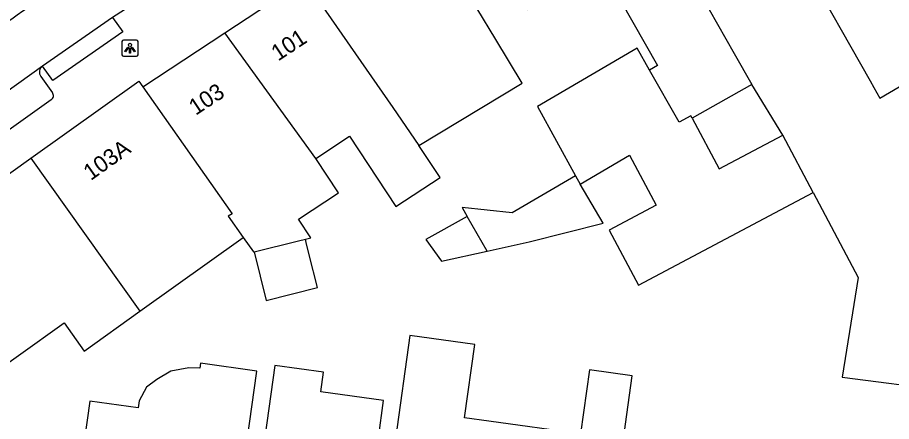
# Model space of a CAD drawing. Extents: x 159718 to 160783, y 383290 to 384030.
# Drawn here: x 160447.6 to 160501.3, y 383337.2 to 383362.1 of the extents above; entities that cross this region are included whole.
import ezdxf

# ---------------------------------------------------------------- set-up
doc = ezdxf.new("R2010")
doc.units = 0
for name, color, linetype in [('IMGEO_Lichtpunt', 7, 'Continuous'), ('IMGEO_Pand', 7, 'Continuous'), ('IMGEO_Pand_nummerreeks', 7, 'Continuous'), ('IMGEO_Rijbaan_lokaal_open', 7, 'Continuous'), ('IMGEO_Voetpad_open', 7, 'Continuous')]:
    doc.layers.add(name, color=color, linetype=linetype)

msp = doc.modelspace()

# ---------------------------------------------------------------- linework, layer by layer
at = {"layer": 'IMGEO_Lichtpunt'}
for p, q in [((160453.989, 383360.581), (160453.989, 383359.774)), ((160453.989, 383360.581), (160453.989, 383359.774)), ((160454.891, 383360.676), (160454.083, 383360.676)), ((160454.891, 383360.676), (160454.083, 383360.676)), ((160454.985, 383359.774), (160454.985, 383360.581)), ((160454.985, 383359.774), (160454.985, 383360.581)), ((160454.083, 383359.68), (160454.891, 383359.68)), ((160454.083, 383359.68), (160454.891, 383359.68))]:
    msp.add_line(p, q, dxfattribs=at)
for points in [[(160454.363, 383360.245), (160454.402, 383360.217), (160454.214, 383359.955), (160454.176, 383359.982), (160454.363, 383360.245)], [(160454.465, 383360.197), (160454.512, 383360.197), (160454.512, 383359.875), (160454.465, 383359.875), (160454.465, 383360.197)], [(160454.575, 383360.217), (160454.613, 383360.244), (160454.8, 383359.982), (160454.761, 383359.954), (160454.575, 383360.217)]]:
    msp.add_lwpolyline(points, dxfattribs=at)
msp.add_circle((160454.488, 383360.379), 0.0994, dxfattribs=at)
for centre, start, end in [((160454.083, 383360.581), 90, 180), ((160454.083, 383360.581), 90, 180), ((160454.891, 383360.581), 0, 90), ((160454.891, 383360.581), 0, 90), ((160454.083, 383359.774), 180, 270), ((160454.083, 383359.774), 180, 270), ((160454.891, 383359.774), 270, 0), ((160454.891, 383359.774), 270, 360)]:
    msp.add_arc(centre, 0.0946, start, end, dxfattribs=at)
at = {"layer": 'IMGEO_Pand'}
for points in [[(160482.934, 383375.203), (160491.645, 383359.858), (160492.727, 383357.952)], [(160474.49, 383370.418), (160476.949, 383366.065), (160478.765, 383362.85), (160478.932, 383362.554), (160481.205, 383363.833), (160482.02, 383364.291), (160482.405, 383363.614), (160483.893, 383364.459), (160486.934, 383359.106), (160486.44, 383358.826)], [(160472.243, 383354.191), (160478.604, 383358.023), (160476.988, 383360.706), (160474.653, 383364.584), (160472.034, 383368.843)], [(160495.919, 383365.354), (160500, 383358.164), (160500.229, 383357.761), (160500.597, 383357.113), (160504.871, 383359.614), (160506.61, 383356.155), (160506.076, 383351.936), (160510.595, 383351.363)], [(160460.32, 383361.128), (160465.222, 383364.356)], [(160465.222, 383364.356), (160470.655, 383356.532), (160472.243, 383354.191)], [(160455.281, 383357.809), (160460.32, 383361.128)], [(160465.92, 383353.41), (160460.32, 383361.128)], [(160486.44, 383358.826), (160485.672, 383360.178), (160479.547, 383356.594), (160481.887, 383352.339)], [(160489.062, 383355.871), (160488.983, 383356.02), (160488.253, 383355.633), (160486.44, 383358.826)], [(160448.396, 383353.416), (160455.036, 383358.149), (160455.281, 383357.809)], [(160492.727, 383357.952), (160489.062, 383355.871)], [(160494.636, 383354.831), (160492.727, 383357.952)], [(160455.281, 383357.809), (160460.761, 383350.009), (160460.533, 383349.859), (160461.455, 383348.546)], [(160489.062, 383355.871), (160490.72, 383352.755), (160494.636, 383354.831)], [(160465.92, 383353.41), (160467.985, 383354.772), (160470.84, 383350.442), (160473.567, 383352.239), (160472.243, 383354.191)], [(160496.503, 383351.311), (160494.636, 383354.831)], [(160482.17, 383351.824), (160485.208, 383353.602), (160486.836, 383350.53), (160483.956, 383349.003), (160485.753, 383345.612), (160496.503, 383351.311)], [(160439.387, 383346.996), (160448.396, 383353.416)], [(160448.396, 383353.416), (160455.096, 383344.015)], [(160465.277, 383348.446), (160465.604, 383348.527), (160464.85, 383349.671), (160467.314, 383351.295), (160465.92, 383353.41)], [(160481.887, 383352.339), (160477.991, 383350.058), (160474.917, 383350.38), (160475.224, 383349.845)], [(160481.887, 383352.339), (160482.17, 383351.824)], [(160476.45, 383347.71), (160479.029, 383348.286), (160483.594, 383349.424), (160482.17, 383351.824)], [(160496.503, 383351.311), (160499.273, 383346.085), (160498.286, 383339.955), (160504.652, 383339.145)], [(160475.224, 383349.845), (160472.682, 383348.427), (160473.649, 383347.085), (160476.45, 383347.71)], [(160476.45, 383347.71), (160475.224, 383349.845)], [(160455.096, 383344.015), (160461.455, 383348.546)], [(160461.455, 383348.546), (160462.079, 383347.657), (160462.118, 383347.667)], [(160462.118, 383347.667), (160464.847, 383348.341), (160465.277, 383348.446)], [(160462.118, 383347.667), (160462.856, 383344.682), (160466.014, 383345.463), (160465.513, 383347.49), (160465.328, 383348.24), (160465.277, 383348.446)], [(160444.801, 383339.293), (160450.429, 383343.303), (160451.665, 383341.569), (160455.096, 383344.015)], [(160485.367, 383340.053), (160482.742, 383340.419), (160482.192, 383336.474), (160476.551, 383337.261), (160475.059, 383337.469), (160475.686, 383341.966), (160471.698, 383342.522), (160470.814, 383336.177), (160470.215, 383331.892), (160469.525, 383326.939), (160483.273, 383325.024), (160483.963, 383329.977), (160484.56, 383334.256), (160485.367, 383340.053)], [(160461.832, 383337.116), (160462.284, 383340.339), (160458.825, 383340.824), (160458.78, 383340.51), (160458.111, 383340.534), (160456.999, 383340.338), (160456.147, 383339.822), (160455.507, 383339.338), (160455.056, 383338.517), (160454.994, 383338.069), (160452.013, 383338.484), (160451.504, 383334.832), (160451.085, 383334.395), (160450.823, 383333.766), (160450.89, 383333.123), (160451.191, 383332.579), (160450.784, 383329.662), (160460.582, 383328.175), (160461.272, 383333.128), (160461.832, 383337.116)], [(160469.762, 383336.24), (160470.075, 383338.53), (160466.214, 383339.068), (160466.38, 383340.265), (160463.391, 383340.682), (160462.9, 383337.161), (160462.328, 383333.057), (160461.638, 383328.104), (160468.506, 383327.147), (160469.196, 383332.1), (160469.762, 383336.24)]]:
    msp.add_lwpolyline(points, dxfattribs=at)
at = {"layer": 'IMGEO_Rijbaan_lokaal_open'}
for points in [[(160457.166, 383364.486), (160453.405, 383362.062)], [(160453.405, 383362.062), (160449.101, 383359.083)], [(160449.101, 383359.083), (160425.529, 383342.179), (160420.378, 383338.346)]]:
    msp.add_lwpolyline(points, dxfattribs=at)
msp.add_arc((160570.774, 383186.65), 214.484, 122.49811, 126.06695, dxfattribs=at)
at = {"layer": 'IMGEO_Voetpad_open'}
for points in [[(160453.405, 383362.062), (160454.053, 383361.179), (160449.743, 383358.204), (160449.101, 383359.083)], [(160449.001, 383358.438), (160449.712, 383357.437)], [(160449.639, 383357.011), (160422.969, 383337.983), (160422.214, 383337.313)]]:
    msp.add_lwpolyline(points, dxfattribs=at)
for centre, radius, start, end in [((160449.401, 383358.706), 0.481, 128.5078, 213.8664), ((160449.492, 383357.255), 0.285, 301.0629, 39.4894)]:
    msp.add_arc(centre, radius, start, end, dxfattribs=at)

# ---------------------------------------------------------------- texts
at = {"layer": 'IMGEO_Pand_nummerreeks'}
for s, rotation, p in [('101', 33.3691, (160463.594, 383359.357)), ('103', 33.3576, (160458.529, 383356.022)), ('103A', 35.4661, (160452.076, 383352.014))]:
    msp.add_text(s, height=1, rotation=rotation, dxfattribs=at).set_placement(p)

doc.saveas('drawing.dxf')
